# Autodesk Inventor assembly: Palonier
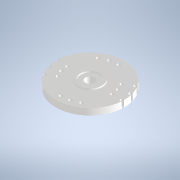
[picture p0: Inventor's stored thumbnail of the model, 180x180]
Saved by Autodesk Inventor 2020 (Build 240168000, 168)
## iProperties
Created: 2012-04
Part Number: Palonier
Document SubType Name: Assembly
Designer: bruno
Sending System: SolidWorks 2010
Last Author: FBruyere
Last Saved: 2012-04-07
Author: bruno
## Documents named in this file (3)
- C:\Users\bruno\Documents\1-Cours-2023-24\Maquettes-Inventor\Pince-robot-Dobot\HS422\Palonier.iam
- C:\Users\bruno\Documents\1-Cours-2023-24\Maquettes-Inventor\Pince-robot-Dobot\HS422\axe_HS422.ipt
- C:\Users\bruno\Documents\1-Cours-2023-24\Maquettes-Inventor\Pince-robot-Dobot\HS422\palonnier_HS422.ipt
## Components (2 placed, 2 different names)
1. axe_HS422:1
2. palonnier_HS422:1
